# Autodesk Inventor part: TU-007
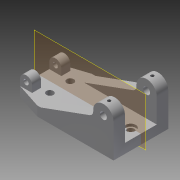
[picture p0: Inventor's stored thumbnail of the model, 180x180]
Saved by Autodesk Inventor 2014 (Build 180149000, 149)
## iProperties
Created: 2008-07
Part Number: TU-007
Document SubType Name: Modeling
Designer: PN
Density: 7.75 g/cm^3
Material: Stainless Steel, 440C
Description: Cylinder Base
Mass: 2332.18 g
Surface Area: 522.777 cm^2
Volume: 300.927 cm^3
Appearance: Steel
Author: PN
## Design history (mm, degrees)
sketch "Sketch1"
  geometry: L1 (0, 0)-(-160, 0); L2 (-160, 0)-(-160, 86); L3 (-160, 86)-(0, 86); L4 (0, 86)-(0, 0)
  constraints: 8 end point, 2 parallel, 1 horizontal, 1 perpendicular
  dimensions: "d0" = 160 distance of L1.start L1.end; "d1" = 86 distance of L3.end L1.start
extrude "Extrusion1" new body sketch "Sketch1" distance "d2" = 15; taper "d3" = 0 deg
sketch "Sketch2"
  geometry: L1 (160, 15)-(0, 15) reference; L2 (160, 0)-(0, 0) reference; L3 (160, 0)-(160, 15) reference; L4 (160, 15)-(160, 53); L5 (128, 53)-(128, 45); L6 (128, 45)-(45.576, 15); A1 r 16 centre (144, 53) between (160, 53) and (128, 53)
  constraints: 6 end point, 2 point on circle, 2 tangent, 1 centre point, 1 collinear, 1 parallel, 1 point on line
  dimensions: "d4" = 16 radius of A1; "d5" = 53 distance from line of A1.centre L2; "d6" = 20 deg angle of L1 L6; "d7" = 8 distance of L5.start L5.end
extrude "Extrusion2" join sketch "Sketch2" distance "d8" = 18; taper "d9" = 0 deg
fillet "Fillet1" dims "d19" = 8
hole "Hole1" diameter "d12" = 11; stored, may be unused: countersink angle "d16" = 90 deg, drill point angle "d18" = 118 deg; dims "d10" = 10, "d11" = 10, "d13" = 6, "d14" = 4, "d15" = 2, "d17" = 8
workplane "Work Plane1"
mirror "Mirror1"
workplane "Work Plane2"
sketch "Sketch3"
  geometry: L1 (45.576, 15)-(0, 15) reference; L2 (0, 15)-(0, 25); L3 (19, 25)-(19, 15); L4 (160, 0)-(0, 0) reference; A1 r 9.5 centre (9.5, 25) between (19, 25) and (0, 25)
  constraints: 4 end point, 2 perpendicular, 2 point on circle, 2 tangent, 1 centre point, 1 point on line
  dimensions: "d21" = 9.5 radius of A1; "d22" = 25 distance from line of A1.centre L4
extrude "Extrusion3" join sketch "Sketch3" distance "d23" = 14; taper "d24" = 0 deg
hole "Hole2" diameter "d27" = 8; stored, may be unused: countersink angle "d31" = 90 deg, drill point angle "d33" = 118 deg; dims "d25" = 10, "d26" = 10, "d28" = 6, "d29" = 4, "d30" = 2, "d32" = 8
mirror "Mirror2"
chamfer "Chamfer1" distance "d34" = 13; stored, may be unused: second distance "d35" = 40, angle "d36" = 45 deg
chamfer "Chamfer2" distance "d37" = 13; stored, may be unused: second distance "d38" = 40, angle "d39" = 45 deg
workplane "Work Plane3"
sketch "Sketch4"
  geometry: L1 (-16, 18)-(16, 18) reference; L2 (-16, 0)-(16, 0) reference; L3 (-16, 68)-(16, 68) reference; L4 (-16, 86)-(16, 86) reference; L5 (0, 86)-(0, 68); L6 (0, 18)-(0, 0); 2 further points
  constraints: 6 midpoint, 4 end point
hole "Hole3" sketch "Sketch4" at (0, 77), (0, 9) diameter "d40" = 4.917; stored, may be unused: countersink angle "d44" = 90 deg, drill point angle "d46" = 118 deg; dims "d41" = 6, "d42" = 4, "d43" = 2, "d45" = 8
sketch "Sketch5"
  geometry: L1 (-160, 27)-(-160, 59) reference; L2 (32, 43)-(-192, 43) reference; 3 further points
  constraints: 1 vertical alignment
  dimensions: "d47" = 16 distance from line of point (-127, 59) L2; "d48" = 32 distance of point (-127, 27) point (-127, 59) (= 2 x d47); "d49" = 33 distance from line of point (-127, 27) L1
hole "Hole4" sketch "Sketch5" at (-127, 59), (-127, 27) diameter "d50" = 11; stored, may be unused: countersink angle "d54" = 90 deg, drill point angle "d56" = 118 deg; dims "d51" = 6, "d52" = 4, "d53" = 2, "d55" = 8
sketch "Sketch6"
  geometry: L1 (0, 68)-(0, 18) reference; L2 (-120, 86)-(-114.424, 86) reference; L3 (0, 43)-(-16, 43); 1 further point
  constraints: 2 end point, 1 midpoint, 1 parallel
  dimensions: "d57" = 16 distance of L3.start L3.end
hole "Hole5" sketch "Sketch6" at (-16, 43) diameter "d58" = 11; stored, may be unused: countersink angle "d62" = 90 deg, drill point angle "d64" = 118 deg; dims "d59" = 6, "d60" = 16, "d61" = 4, "d63" = 8
body "Solid1"
